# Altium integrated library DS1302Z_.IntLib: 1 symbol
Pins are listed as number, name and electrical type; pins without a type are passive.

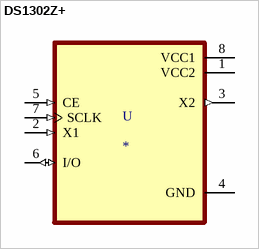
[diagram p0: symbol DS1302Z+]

## DS1302Z+
designator U
Real Time Clock _RTC_ IC Clock/Calendar 31B 3-Wire Serial 8-SOIC _0.154, 3.90mm Width_; MF: Maxim Integrated; MP: DS1302Z
footprint SOIC127P600X175-8N
pins: 1 VCC2 (power), 2 X1 (in), 3 X2 (out), 4 GND (power), 5 CE (in), 6 I/O (io), 7 SCLK (in), 8 VCC1 (power)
